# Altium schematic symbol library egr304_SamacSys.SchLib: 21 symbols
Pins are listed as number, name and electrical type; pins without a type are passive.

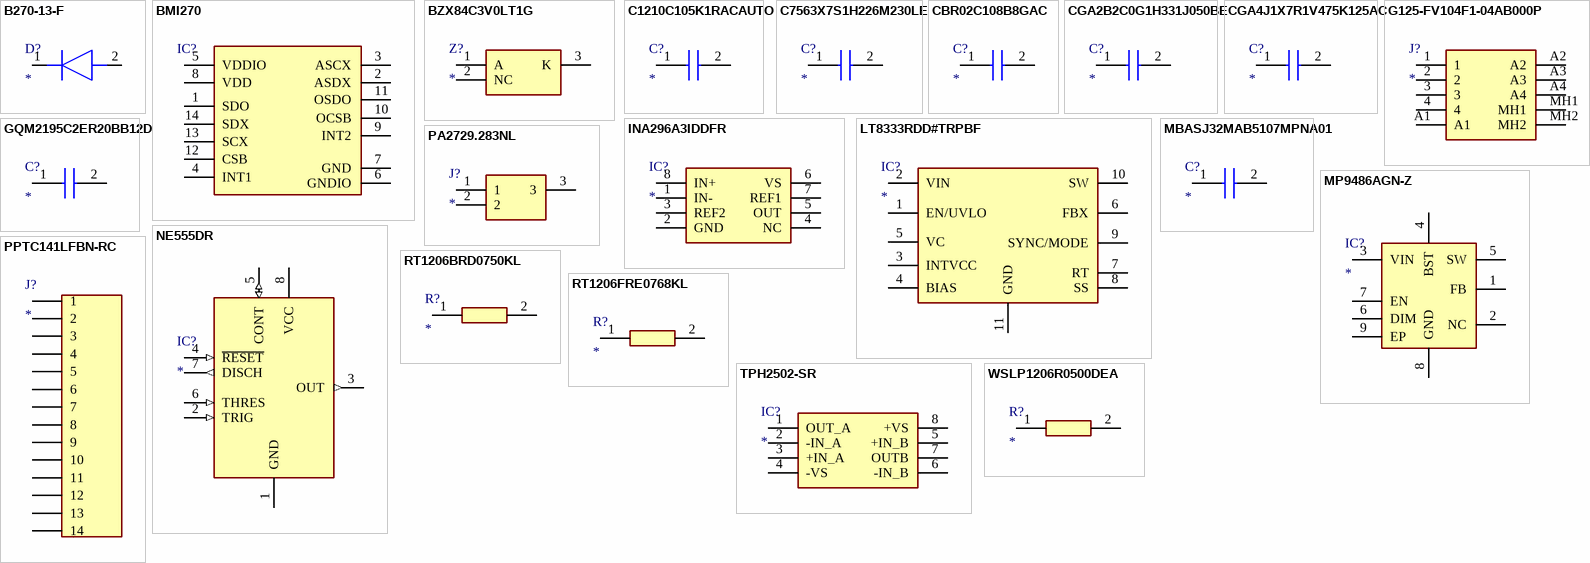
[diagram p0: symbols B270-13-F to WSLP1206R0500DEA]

## B270-13-F
designator D?
Diode; Manufacturer_Name: Diodes Incorporated; Manufacturer_Part_Number: B270-13-F
footprint DIOM5336X250N
pins: 1 K, 2 A

## BMI270
designator IC?  (value not drawn)
IMU
footprint BMI270
pins: 1 SDO, 2 ASDX, 3 ASCX, 4 INT1, 5 VDDIO, 6 GNDIO, 7 GND, 8 VDD, 9 INT2, 10 OCSB, 11 OSDO, 12 CSB, 13 SCX, 14 SDX

## BZX84C3V0LT1G
designator Z?
Zener Diode; Manufacturer_Name: onsemi; Manufacturer_Part_Number: BZX84C3V0LT1G
footprint SOT96P237X111-3N
pins: 1 A, 2 NC, 3 K

## C1210C105K1RACAUTO
designator C?
Capacitor; Manufacturer_Name: Yageo Group; Manufacturer_Part_Number: C1210C105K1RACAUTO
footprint C1210
pins: 1, 2

## C7563X7S1H226M230LE
designator C?
Capacitor; Manufacturer_Name: TDK; Manufacturer_Part_Number: C7563X7S1H226M230LE
footprint CAPC7563X250N
pins: 1, 2

## CBR02C108B8GAC
designator C?
Capacitor; Manufacturer_Name: Yageo Group; Manufacturer_Part_Number: CBR02C108B8GAC
footprint CAPC0603X33N
pins: 1, 2

## CGA2B2C0G1H331J050BE
designator C?
Capacitor; Manufacturer_Name: TDK; Manufacturer_Part_Number: CGA2B2C0G1H331J050BE
footprint CAPC1005X55N
pins: 1, 2

## CGA4J1X7R1V475K125AC
designator C?
Capacitor; Manufacturer_Name: TDK; Manufacturer_Part_Number: CGA4J1X7R1V475K125AC
footprint CGA4J2NP01H223J125AA
pins: 1, 2

## G125-FV104F1-04AB000P
designator J?
Connector; Manufacturer_Name: Harwin; Manufacturer_Part_Number: G125-FV104F1-04AB000P
footprint G125FV104F104AB000P
pins: 1, 2, 3, 4, A1, A2, A3, A4, MH1, MH2

## GQM2195C2ER20BB12D
designator C?
Capacitor; Manufacturer_Name: Murata Electronics; Manufacturer_Part_Number: GQM2195C2ER20BB12D
footprint GQM219
pins: 1, 2

## INA296A3IDDFR
designator IC?
Integrated Circuit; Manufacturer_Name: Texas Instruments; Manufacturer_Part_Number: INA296A3IDDFR
footprint SOT65P280X110-8N
pins: 1 IN-, 2 GND, 3 REF2, 4 NC, 5 OUT, 6 VS, 7 REF1, 8 IN+

## LT8333RDD#TRPBF
designator IC?
Integrated Circuit; Manufacturer_Name: Analog Devices; Manufacturer_Part_Number: LT8333RDD#TRPBF
footprint SON50P300X300X80-11N-D
pins: 1 EN/UVLO, 2 VIN, 3 INTVCC, 4 BIAS, 5 VC, 6 FBX, 7 RT, 8 SS, 9 SYNC/MODE, 10 SW, 11 GND

## MBASJ32MAB5107MPNA01
designator C?
Capacitor; Manufacturer_Name: TAIYO YUDEN; Manufacturer_Part_Number: MBASJ32MAB5107MPNA01
footprint MBASx32x
pins: 1, 2

## MP9486AGN-Z
designator IC?
Integrated Circuit; Manufacturer_Name: Monolithic Power Systems (MPS); Manufacturer_Part_Number: MP9486AGN-Z
footprint SOIC127P600X170-9N
pins: 1 FB, 2 NC, 3 VIN, 4 BST, 5 SW, 6 DIM, 7 EN, 8 GND, 9 EP

## NE555DR
designator IC?
Integrated Circuit; Manufacturer_Name: Texas Instruments; Manufacturer_Part_Number: NE555DR
footprint SOIC127P600X175-8N
pins: 1 GND (power), 2 TRIG (in), 3 OUT (out), 4 ~{RESET} (in), 5 CONT (io), 6 THRES (in), 7 DISCH (out), 8 VCC (power)

## PA2729.283NL
designator J?
Connector; Manufacturer_Name: Yageo Group; Manufacturer_Part_Number: PA2729.283NL
footprint PA2729283NL
pins: 1, 2, 3

## PPTC141LFBN-RC
designator J?
Connector; Manufacturer_Name: Sullins; Manufacturer_Part_Number: PPTC141LFBN-RC
footprint RHDR14W80P0X254_1X14_3606X254X850P
pins: 1, 2, 3, 4, 5, 6, 7, 8, 9, 10, 11, 12, 13, 14

## RT1206BRD0750KL
designator R?
Resistor; Manufacturer_Name: Yageo Group; Manufacturer_Part_Number: RT1206BRD0750KL
footprint CAPC3116X65N
pins: 1, 2

## RT1206FRE0768KL
designator R?
Resistor; Manufacturer_Name: Yageo Group; Manufacturer_Part_Number: RT1206FRE0768KL
footprint RESC3116X65N
pins: 1, 2

## TPH2502-SR
designator IC?
Integrated Circuit; Manufacturer_Name: 3Peak Incorporated; Manufacturer_Part_Number: TPH2502-SR
footprint SOIC127P600X175-8N
pins: 1 OUT_A, 2 -IN_A, 3 +IN_A, 4 -VS, 5 +IN_B, 6 -IN_B, 7 OUTB, 8 +VS

## WSLP1206R0500DEA
designator R?
Resistor; Manufacturer_Name: Vishay; Manufacturer_Part_Number: WSLP1206R0500DEA
footprint RESC3216X89N
pins: 1, 2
